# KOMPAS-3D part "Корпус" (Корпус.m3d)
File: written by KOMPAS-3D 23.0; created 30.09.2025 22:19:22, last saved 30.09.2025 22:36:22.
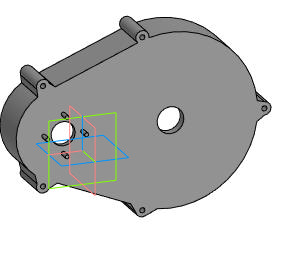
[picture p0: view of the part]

Document properties: Автор: Inspektor_Kot; Полное имя файла: C:\Users\Lost\Desktop\Варианты\Вариант 7\Вариант 7\Корпус.m3d

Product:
- Part/product: Корпус
    Масса: 0.846874

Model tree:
1. Эскиз:1  (with: Операция без истории:1)  (labels: Движок 12В)
2. Элемент выдавливания:1  (with: Операция без истории:1)  (labels: Движок 12В)
     Расстояние 1 = -8
3. Эскиз:2  (with: Элемент выдавливания:1, Элемент выдавливания:2)
4. Элемент выдавливания:2
     Расстояние 1 = 4
5. Эскиз:3  (with: Элемент выдавливания:2, Элемент выдавливания:1)
6. Элемент выдавливания:3  (with: Операция без истории:1)
     Расстояние 1 = 3
7. Эскиз:4  (with: Элемент выдавливания:2)
8. Элемент выдавливания:4
     Расстояние 1 = 28
9. Эскиз:5  (with: Элемент выдавливания:2, Элемент выдавливания:4)
10. Элемент выдавливания:5  (with: Элемент выдавливания:4)
     Расстояние 1 = -32
11. Эскиз:8  (with: Элемент выдавливания:2)
12. Элемент выдавливания:8
     Расстояние 2 = 10

Referenced files in I:\Autodesk Inventor Projects\ИМ-ИТ ЦД\Вариант 7\: Мотор-редуктор.a3d
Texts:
  Цилиндрическое зубчатое зацепление1\Цилиндрическое зубчатое зацепление21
